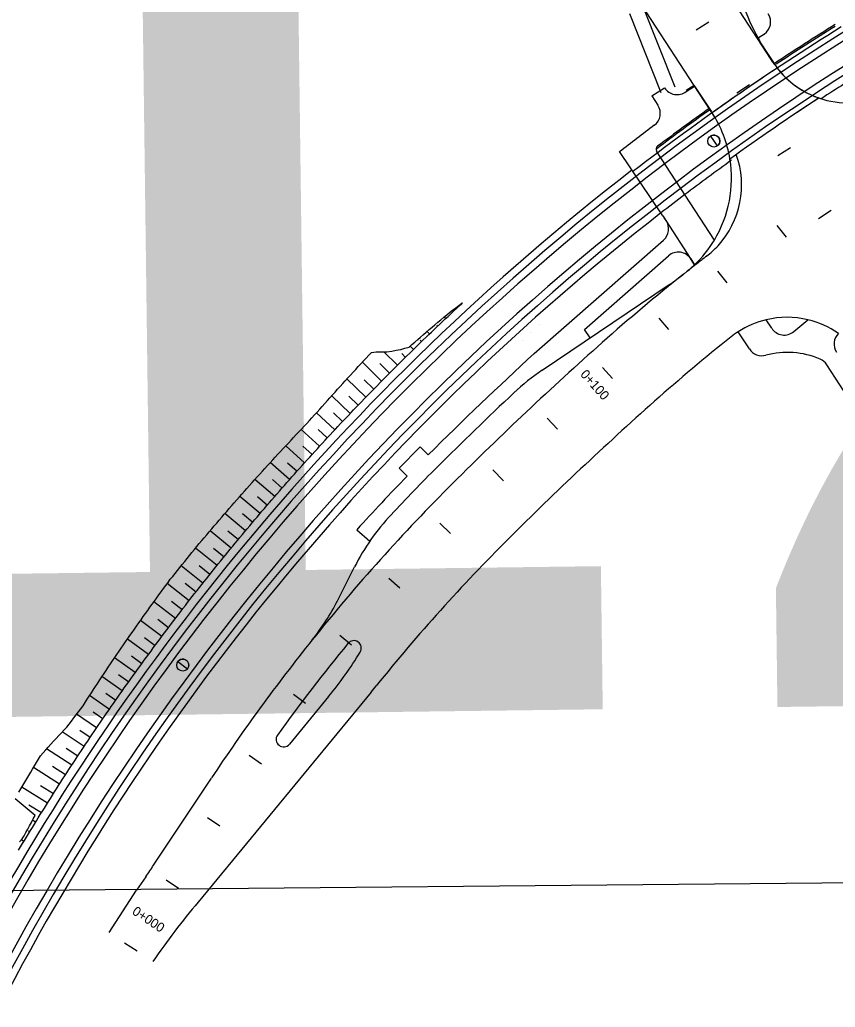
# Model space of a CAD drawing. Extents: x 6503541 to 6503743, y 5888004 to 5888145.
# Drawn here: x 6503659.417 to 6503662.029, y 5888075.351 to 5888078.516 of the extents above; entities that cross this region are included whole.
import ezdxf

# ---------------------------------------------------------------- set-up
doc = ezdxf.new("R2010")
doc.units = 0
doc.layers.add('12', color=7, linetype='Continuous')
doc.layers.add('tabela', color=7, linetype='Continuous')

msp = doc.modelspace()

# ---------------------------------------------------------------- linework, layer by layer
at = {"layer": '12'}
for p, q in [((6503661.7805, 5888078.4554), (6503661.1379, 5888079.444)), ((6503661.5776, 5888078.3052), (6503660.8946, 5888079.3559)), ((6503661.5165, 5888078.2997), (6503661.4141, 5888078.5568)), ((6503661.4719, 5888078.282), (6503661.3713, 5888078.5346)), ((6503661.8022, 5888078.4698), (6503661.7804, 5888078.4556)), ((6503661.7804, 5888078.4556), (6503661.8396, 5888078.3656)), ((6503661.81, 5888078.4101), (6503661.7805, 5888078.4554)), ((6503661.8299, 5888078.3797), (6503661.81, 5888078.4101)), ((6503661.5517, 5888078.2856), (6503661.5789, 5888078.3033)), ((6503661.5776, 5888078.3052), (6503661.5519, 5888078.2885)), ((6503661.6301, 5888078.2245), (6503661.5776, 5888078.3052)), ((6503661.5789, 5888078.3033), (6503661.6315, 5888078.2224)), ((6503661.4421, 5888078.2714), (6503661.4824, 5888078.2976)), ((6503661.4421, 5888078.2714), (6503661.4612, 5888078.2422)), ((6503661.6348, 5888078.2173), (6503661.6301, 5888078.2245)), ((6503661.644, 5888078.2032), (6503661.6301, 5888078.2245)), ((6503661.6348, 5888078.2173), (6503661.6349, 5888078.2171)), ((6503661.477, 5888077.8876), (6503661.3381, 5888078.093)), ((6503661.642, 5888077.8099), (6503661.4572, 5888078.0942)), ((6503661.477, 5888077.8876), (6503661.5768, 5888077.734)), ((6503661.4872, 5888077.8723), (6503661.481, 5888077.8814)), ((6503661.0651, 5888077.4464), (6503661.4791, 5888077.8093)), ((6503661.5789, 5888077.7308), (6503661.5568, 5888077.7649)), ((6503661.2256, 5888077.5233), (6503661.495, 5888077.7593)), ((6503661.5668, 5888077.7494), (6503661.5789, 5888077.7308)), ((6503661.0905, 5888077.3927), (6503661.4977, 5888077.667)), ((6503660.8346, 5888077.6079), (6503660.8339, 5888077.6087)), ((6503660.8068, 5888077.5849), (6503660.8082, 5888077.5834)), ((6503660.7819, 5888077.5588), (6503660.7769, 5888077.5641)), ((6503661.8257, 5888077.5273), (6503661.8082, 5888077.5543)), ((6503661.8968, 5888077.5166), (6503661.9419, 5888077.5543)), ((6503660.7297, 5888077.5092), (6503660.7221, 5888077.5172)), ((6503660.7526, 5888077.5374), (6503660.7558, 5888077.5341)), ((6503661.0537, 5888077.5136), (6503661.054, 5888077.5132)), ((6503661.0805, 5888077.5376), (6503661.0805, 5888077.5376)), ((6503661.2441, 5888077.4961), (6503661.2256, 5888077.5233)), ((6503661.7543, 5888077.461), (6503661.7186, 5888077.516)), ((6503660.6993, 5888077.4889), (6503660.7038, 5888077.4842)), ((6503661.0273, 5888077.4891), (6503661.027, 5888077.4894)), ((6503660.6267, 5888077.4086), (6503660.5835, 5888077.452)), ((6503660.678, 5888077.4591), (6503660.6675, 5888077.4698)), ((6503660.5759, 5888077.3576), (6503660.5142, 5888077.4185)), ((6503660.6406, 5888077.4458), (6503660.6523, 5888077.4339)), ((6503660.5702, 5888077.4141), (6503660.6012, 5888077.3831)), ((6503662.0996, 5888077.2602), (6503662.002, 5888077.4103)), ((6503660.5255, 5888077.3061), (6503660.4649, 5888077.3649)), ((6503660.5201, 5888077.3618), (6503660.5507, 5888077.3319)), ((6503660.4757, 5888077.2542), (6503660.4162, 5888077.3108)), ((6503660.4705, 5888077.3091), (6503660.5005, 5888077.2802)), ((6503660.4263, 5888077.2018), (6503660.3678, 5888077.2564)), ((6503660.4215, 5888077.2558), (6503660.4509, 5888077.2281)), ((6503660.3773, 5888077.149), (6503660.3185, 5888077.203)), ((6503660.3725, 5888077.2026), (6503660.4017, 5888077.1755)), ((6503660.3289, 5888077.0957), (6503660.2686, 5888077.1501)), ((6503660.3233, 5888077.1495), (6503660.3531, 5888077.1224)), ((6503660.6323, 5888077.0786), (6503660.6997, 5888077.147)), ((6503660.7253, 5888077.1217), (6503660.6997, 5888077.147)), ((6503660.2809, 5888077.042), (6503660.2192, 5888077.0967)), ((6503660.2743, 5888077.0962), (6503660.3049, 5888077.0689)), ((6503660.6323, 5888077.0786), (6503660.6579, 5888077.0534)), ((6503660.2335, 5888076.9879), (6503660.1703, 5888077.0428)), ((6503660.2259, 5888077.0424), (6503660.2571, 5888077.015)), ((6503660.1865, 5888076.9333), (6503660.1219, 5888076.9884)), ((6503660.178, 5888076.9882), (6503660.2099, 5888076.9607)), ((6503660.14, 5888076.8783), (6503660.074, 5888076.9336)), ((6503660.1305, 5888076.9335), (6503660.1632, 5888076.9059)), ((6503660.094, 5888076.8229), (6503660.0266, 5888076.8783)), ((6503660.0836, 5888076.8784), (6503660.117, 5888076.8507)), ((6503660.4968, 5888076.8816), (6503660.5378, 5888076.8446)), ((6503660.0486, 5888076.7671), (6503659.9798, 5888076.8226)), ((6503660.0372, 5888076.8228), (6503660.0713, 5888076.7951)), ((6503660.0036, 5888076.7108), (6503659.9337, 5888076.7662)), ((6503659.9913, 5888076.7668), (6503660.026, 5888076.739)), ((6503660.4345, 5888076.654), (6503660.4892, 5888076.7624)), ((6503659.9592, 5888076.6542), (6503659.8889, 5888076.7088)), ((6503659.9462, 5888076.7102), (6503659.9813, 5888076.6826)), ((6503659.9153, 5888076.5971), (6503659.8459, 5888076.65)), ((6503659.9023, 5888076.6526), (6503659.9372, 5888076.6257)), ((6503659.8591, 5888076.5945), (6503659.8935, 5888076.5685)), ((6503659.8719, 5888076.5397), (6503659.8036, 5888076.5908)), ((6503659.829, 5888076.4819), (6503659.7618, 5888076.5312)), ((6503659.8165, 5888076.5359), (6503659.8504, 5888076.5108)), ((6503659.7866, 5888076.4236), (6503659.7206, 5888076.4712)), ((6503659.7744, 5888076.477), (6503659.8077, 5888076.4528)), ((6503659.7448, 5888076.365), (6503659.6801, 5888076.4108)), ((6503659.733, 5888076.4177), (6503659.7657, 5888076.3944)), ((6503659.7036, 5888076.306), (6503659.6402, 5888076.3499)), ((6503659.6921, 5888076.358), (6503659.7241, 5888076.3356)), ((6503660.5423, 5888076.3612), (6503659.9879, 5888075.6883)), ((6503660.4063, 5888076.347), (6503660.2806, 5888076.1945)), ((6503659.6628, 5888076.2467), (6503659.5989, 5888076.2901)), ((6503659.6518, 5888076.2979), (6503659.6831, 5888076.2764)), ((6503659.6226, 5888076.1869), (6503659.5524, 5888076.2337)), ((6503659.6096, 5888076.239), (6503659.6426, 5888076.2168)), ((6503659.5651, 5888076.1817), (6503659.6027, 5888076.1569)), ((6503659.583, 5888076.1268), (6503659.5027, 5888076.1792)), ((6503659.5438, 5888076.0664), (6503659.4608, 5888076.1196)), ((6503659.5215, 5888076.1237), (6503659.5633, 5888076.0967)), ((6503659.5053, 5888076.0056), (6503659.4235, 5888076.0569)), ((6503659.4833, 5888076.0621), (6503659.5245, 5888076.036)), ((6503659.8456, 5888075.807), (6503660.0306, 5888076.086)), ((6503659.4457, 5888076.0002), (6503659.4862, 5888075.975)), ((6503659.4673, 5888075.9444), (6503659.4574, 5888075.9505)), ((6503659.4444, 5888075.9162), (6503659.4485, 5888075.9137)), ((6503659.4299, 5888075.8829), (6503659.4218, 5888075.8878)), ((6503659.8201, 5888075.7694), (6503659.7908, 5888075.727)), ((6503659.7034, 5888075.5913), (6503659.7908, 5888075.727))]:
    msp.add_line(p, q, dxfattribs=at)
for points in [[(6503661.5838, 5888078.4829), (6503661.624, 5888078.5091)], [(6503661.7146, 5888078.2817), (6503661.7548, 5888078.3079)], [(6503661.6292, 5888078.1425), (6503661.6516, 5888078.1113)], [(6503661.8454, 5888078.0805), (6503661.8856, 5888078.1066)], [(6503661.9762, 5888077.8793), (6503662.0164, 5888077.9054)], [(6503661.8729, 5888077.8186), (6503661.8436, 5888077.8567)], [(6503661.6827, 5888077.6723), (6503661.6534, 5888077.7103)], [(6503659.413, 5888075.8548), (6503659.4192, 5888075.8652), (6503659.4255, 5888075.8757), (6503659.4318, 5888075.8861), (6503659.438, 5888075.8965), (6503659.4444, 5888075.9069), (6503659.4507, 5888075.9173), (6503659.457, 5888075.9277), (6503659.4634, 5888075.9381), (6503659.4698, 5888075.9484), (6503659.4761, 5888075.9588), (6503659.4825, 5888075.9691), (6503659.489, 5888075.9795), (6503659.4954, 5888075.9898), (6503659.5019, 5888076.0001), (6503659.5083, 5888076.0104), (6503659.5148, 5888076.0207), (6503659.5213, 5888076.031), (6503659.5278, 5888076.0413), (6503659.5344, 5888076.0515), (6503659.5409, 5888076.0618), (6503659.5475, 5888076.072), (6503659.554, 5888076.0823), (6503659.5606, 5888076.0925), (6503659.5672, 5888076.1027), (6503659.5739, 5888076.1129), (6503659.5805, 5888076.1231), (6503659.5872, 5888076.1333), (6503659.5938, 5888076.1435), (6503659.6005, 5888076.1536), (6503659.6072, 5888076.1638), (6503659.614, 5888076.1739), (6503659.6207, 5888076.1841), (6503659.6274, 5888076.1942), (6503659.6342, 5888076.2043), (6503659.641, 5888076.2144), (6503659.6478, 5888076.2245), (6503659.6546, 5888076.2346), (6503659.6614, 5888076.2446), (6503659.6683, 5888076.2547), (6503659.6751, 5888076.2647), (6503659.682, 5888076.2748), (6503659.6889, 5888076.2848), (6503659.6958, 5888076.2948), (6503659.7027, 5888076.3048), (6503659.7097, 5888076.3148), (6503659.7166, 5888076.3248), (6503659.7236, 5888076.3348), (6503659.7306, 5888076.3448), (6503659.7376, 5888076.3547), (6503659.7446, 5888076.3647), (6503659.7516, 5888076.3746), (6503659.7586, 5888076.3845), (6503659.7657, 5888076.3944), (6503659.7728, 5888076.4043), (6503659.7799, 5888076.4142), (6503659.787, 5888076.4241), (6503659.7941, 5888076.434), (6503659.8012, 5888076.4438), (6503659.8084, 5888076.4537), (6503659.8155, 5888076.4635), (6503659.8227, 5888076.4733), (6503659.8299, 5888076.4831), (6503659.8371, 5888076.4929), (6503659.8444, 5888076.5027), (6503659.8516, 5888076.5125), (6503659.8588, 5888076.5223), (6503659.8661, 5888076.532), (6503659.8734, 5888076.5418), (6503659.8807, 5888076.5515), (6503659.888, 5888076.5612), (6503659.8954, 5888076.5709), (6503659.9027, 5888076.5806), (6503659.9101, 5888076.5903), (6503659.9174, 5888076.6), (6503659.9248, 5888076.6097), (6503659.9322, 5888076.6193), (6503659.9396, 5888076.629), (6503659.9471, 5888076.6386), (6503659.9545, 5888076.6482), (6503659.962, 5888076.6578), (6503659.9695, 5888076.6674), (6503659.977, 5888076.677), (6503659.9845, 5888076.6866), (6503659.992, 5888076.6961), (6503659.9995, 5888076.7057), (6503660.0071, 5888076.7152), (6503660.0147, 5888076.7247), (6503660.0222, 5888076.7343), (6503660.0298, 5888076.7438), (6503660.0375, 5888076.7533), (6503660.0451, 5888076.7627), (6503660.0527, 5888076.7722), (6503660.0604, 5888076.7817), (6503660.068, 5888076.7911), (6503660.0757, 5888076.8005), (6503660.0834, 5888076.81), (6503660.0911, 5888076.8194), (6503660.0989, 5888076.8288), (6503660.1066, 5888076.8382), (6503660.1144, 5888076.8475), (6503660.1221, 5888076.8569), (6503660.1299, 5888076.8663), (6503660.1377, 5888076.8756), (6503660.1455, 5888076.8849), (6503660.1534, 5888076.8942), (6503660.1612, 5888076.9035), (6503660.1691, 5888076.9128), (6503660.1769, 5888076.9221), (6503660.1848, 5888076.9314), (6503660.1927, 5888076.9406), (6503660.2006, 5888076.9499), (6503660.2086, 5888076.9591), (6503660.2165, 5888076.9683), (6503660.2245, 5888076.9775), (6503660.2324, 5888076.9867), (6503660.2404, 5888076.9959), (6503660.2484, 5888077.0051), (6503660.2564, 5888077.0142), (6503660.2645, 5888077.0234), (6503660.2725, 5888077.0325), (6503660.2806, 5888077.0416), (6503660.2886, 5888077.0507), (6503660.2967, 5888077.0598), (6503660.3048, 5888077.0689), (6503660.3129, 5888077.078), (6503660.321, 5888077.087), (6503660.3292, 5888077.0961), (6503660.3373, 5888077.1051), (6503660.3455, 5888077.1141), (6503660.3537, 5888077.1231), (6503660.3619, 5888077.1321), (6503660.3701, 5888077.1411), (6503660.3783, 5888077.1501), (6503660.3865, 5888077.159), (6503660.3948, 5888077.168), (6503660.4031, 5888077.1769), (6503660.4113, 5888077.1858), (6503660.4196, 5888077.1947), (6503660.4279, 5888077.2036), (6503660.4362, 5888077.2125), (6503660.4446, 5888077.2214), (6503660.4529, 5888077.2302), (6503660.4613, 5888077.239), (6503660.4697, 5888077.2479), (6503660.478, 5888077.2567), (6503660.4864, 5888077.2655), (6503660.4949, 5888077.2743), (6503660.5033, 5888077.2831), (6503660.5117, 5888077.2918), (6503660.5202, 5888077.3006), (6503660.5286, 5888077.3093), (6503660.5371, 5888077.318), (6503660.5456, 5888077.3267), (6503660.5541, 5888077.3354), (6503660.5626, 5888077.3441), (6503660.5712, 5888077.3528), (6503660.5797, 5888077.3615), (6503660.5883, 5888077.3701), (6503660.5969, 5888077.3787), (6503660.6054, 5888077.3874), (6503660.614, 5888077.396), (6503660.6227, 5888077.4046), (6503660.6313, 5888077.4131), (6503660.6399, 5888077.4217), (6503660.6486, 5888077.4303), (6503660.6573, 5888077.4388), (6503660.6659, 5888077.4473), (6503660.6746, 5888077.4558), (6503660.6833, 5888077.4643), (6503660.6921, 5888077.4728), (6503660.7008, 5888077.4813), (6503660.7095, 5888077.4898), (6503660.7183, 5888077.4982), (6503660.7271, 5888077.5066), (6503660.7358, 5888077.5151), (6503660.7446, 5888077.5235), (6503660.7534, 5888077.5319), (6503660.7623, 5888077.5402), (6503660.7711, 5888077.5486), (6503660.78, 5888077.5569), (6503660.7888, 5888077.5653), (6503660.7977, 5888077.5736), (6503660.8066, 5888077.5819), (6503660.8155, 5888077.5902), (6503660.8244, 5888077.5985), (6503660.8333, 5888077.6068), (6503660.8346, 5888077.6079)], [(6503659.414, 5888076.0406), (6503659.4202, 5888076.0512), (6503659.4265, 5888076.0619), (6503659.4327, 5888076.0725), (6503659.439, 5888076.0831), (6503659.4453, 5888076.0937), (6503659.4516, 5888076.1043), (6503659.4579, 5888076.1148), (6503659.4643, 5888076.1254), (6503659.4706, 5888076.136), (6503659.477, 5888076.1465), (6503659.4834, 5888076.1571), (6503659.4913, 5888076.1666), (6503659.4997, 5888076.1759), (6503659.508, 5888076.1851), (6503659.5164, 5888076.1943), (6503659.5248, 5888076.2035), (6503659.5332, 5888076.2127), (6503659.5416, 5888076.2219), (6503659.55, 5888076.2311), (6503659.5585, 5888076.2403), (6503659.5669, 5888076.2494), (6503659.5748, 5888076.2589), (6503659.5823, 5888076.2686), (6503659.5898, 5888076.2784), (6503659.5974, 5888076.2882), (6503659.6049, 5888076.2979), (6503659.6124, 5888076.3076), (6503659.6194, 5888076.3177), (6503659.626, 5888076.3281), (6503659.6327, 5888076.3384), (6503659.6394, 5888076.3487), (6503659.6461, 5888076.359), (6503659.6528, 5888076.3693), (6503659.6595, 5888076.3796), (6503659.6663, 5888076.3899), (6503659.6731, 5888076.4001), (6503659.6798, 5888076.4104), (6503659.6867, 5888076.4206), (6503659.6935, 5888076.4309), (6503659.7003, 5888076.4411), (6503659.7072, 5888076.4513), (6503659.7141, 5888076.4615), (6503659.7209, 5888076.4717), (6503659.7279, 5888076.4818), (6503659.7348, 5888076.492), (6503659.7417, 5888076.5021), (6503659.7487, 5888076.5123), (6503659.7557, 5888076.5224), (6503659.7627, 5888076.5325), (6503659.7697, 5888076.5426), (6503659.7767, 5888076.5527), (6503659.7838, 5888076.5628), (6503659.7909, 5888076.5728), (6503659.7979, 5888076.5829), (6503659.8051, 5888076.5929), (6503659.8122, 5888076.603), (6503659.8193, 5888076.613), (6503659.8265, 5888076.623), (6503659.8336, 5888076.633), (6503659.8408, 5888076.643), (6503659.848, 5888076.653), (6503659.8553, 5888076.6629), (6503659.8625, 5888076.6729), (6503659.8698, 5888076.6828), (6503659.8771, 5888076.6927), (6503659.8843, 5888076.7026), (6503659.8917, 5888076.7125), (6503659.8986, 5888076.7227), (6503659.9066, 5888076.7321), (6503659.9141, 5888076.7418), (6503659.9218, 5888076.7514), (6503659.9295, 5888076.761), (6503659.9372, 5888076.7706), (6503659.945, 5888076.7802), (6503659.9527, 5888076.7897), (6503659.9605, 5888076.7993), (6503659.9683, 5888076.8088), (6503659.9762, 5888076.8182), (6503659.984, 5888076.8277), (6503659.9919, 5888076.8372), (6503659.9998, 5888076.8466), (6503660.0078, 5888076.856), (6503660.0157, 5888076.8654), (6503660.0236, 5888076.8748), (6503660.0316, 5888076.8842), (6503660.0396, 5888076.8935), (6503660.0476, 5888076.9029), (6503660.0556, 5888076.9122), (6503660.0636, 5888076.9216), (6503660.0716, 5888076.9309), (6503660.0797, 5888076.9402), (6503660.0877, 5888076.9495), (6503660.0958, 5888076.9587), (6503660.1039, 5888076.968), (6503660.112, 5888076.9773), (6503660.1202, 5888076.9865), (6503660.1283, 5888076.9957), (6503660.1364, 5888077.0049), (6503660.1446, 5888077.0141), (6503660.1528, 5888077.0233), (6503660.161, 5888077.0325), (6503660.1692, 5888077.0416), (6503660.1774, 5888077.0508), (6503660.1857, 5888077.0599), (6503660.1939, 5888077.069), (6503660.2022, 5888077.0781), (6503660.2105, 5888077.0872), (6503660.2188, 5888077.0963), (6503660.2271, 5888077.1053), (6503660.2354, 5888077.1144), (6503660.2438, 5888077.1234), (6503660.2521, 5888077.1324), (6503660.2605, 5888077.1414), (6503660.2689, 5888077.1504), (6503660.2773, 5888077.1594), (6503660.2857, 5888077.1684), (6503660.2941, 5888077.1773), (6503660.3025, 5888077.1862), (6503660.311, 5888077.1952), (6503660.3195, 5888077.2041), (6503660.328, 5888077.213), (6503660.3362, 5888077.222), (6503660.3445, 5888077.2311), (6503660.3528, 5888077.2402), (6503660.3612, 5888077.2492), (6503660.3695, 5888077.2583), (6503660.3777, 5888077.2674), (6503660.3858, 5888077.2766), (6503660.394, 5888077.2859), (6503660.4021, 5888077.2951), (6503660.4103, 5888077.3042), (6503660.4185, 5888077.3134), (6503660.4267, 5888077.3226), (6503660.4349, 5888077.3317), (6503660.4432, 5888077.3409), (6503660.4514, 5888077.35), (6503660.4597, 5888077.3591), (6503660.468, 5888077.3682), (6503660.4763, 5888077.3773), (6503660.4846, 5888077.3864), (6503660.4929, 5888077.3954), (6503660.5013, 5888077.4045), (6503660.5096, 5888077.4135), (6503660.518, 5888077.4225), (6503660.5264, 5888077.4315), (6503660.5348, 5888077.4404), (6503660.5433, 5888077.4493), (6503660.5588, 5888077.4512), (6503660.5754, 5888077.452), (6503660.5927, 5888077.452), (6503660.6082, 5888077.4538), (6503660.6227, 5888077.4565), (6503660.6371, 5888077.4593), (6503660.6507, 5888077.4629), (6503660.664, 5888077.4667), (6503660.6732, 5888077.4748), (6503660.6824, 5888077.4828), (6503660.6916, 5888077.4908), (6503660.7008, 5888077.4988), (6503660.71, 5888077.5068), (6503660.7192, 5888077.5148), (6503660.7285, 5888077.5227), (6503660.7377, 5888077.5307), (6503660.747, 5888077.5386), (6503660.7563, 5888077.5466), (6503660.7655, 5888077.5545), (6503660.7748, 5888077.5624), (6503660.7844, 5888077.57), (6503660.794, 5888077.5775), (6503660.8036, 5888077.5851), (6503660.8133, 5888077.5926), (6503660.8229, 5888077.6001), (6503660.8339, 5888077.6087)], [(6503661.4962, 5888077.5227), (6503661.4654, 5888077.5595)], [(6503661.2836, 5888077.4016), (6503661.3157, 5888077.3659)], [(6503661.1391, 5888077.2041), (6503661.1063, 5888077.2392)], [(6503660.966, 5888077.0386), (6503660.9324, 5888077.073)], [(6503660.797, 5888076.8693), (6503660.7624, 5888076.9026)], [(6503660.6346, 5888076.6938), (6503660.5987, 5888076.7257)], [(6503660.4794, 5888076.5121), (6503660.4423, 5888076.5425)], [(6503659.9235, 5888076.4592), (6503659.9543, 5888076.4363)], [(6503660.3316, 5888076.3242), (6503660.2933, 5888076.3531)], [(6503660.1914, 5888076.1306), (6503660.152, 5888076.158)], [(6503659.4161, 5888075.8813), (6503659.4243, 5888075.8906), (6503659.4307, 5888075.9009), (6503659.4365, 5888075.9117), (6503659.4422, 5888075.9225), (6503659.448, 5888075.9332), (6503659.4538, 5888075.9439), (6503659.4596, 5888075.9547), (6503659.4655, 5888075.9654), (6503659.4016, 5888076.0193)], [(6503660.0579, 5888075.9318), (6503660.0179, 5888075.9583)], [(6503659.9253, 5888075.7318), (6503659.8853, 5888075.7583)], [(6503659.7526, 5888075.5583), (6503659.7926, 5888075.5318)]]:
    msp.add_lwpolyline(points, dxfattribs=at)
for centre in [(6503661.6404, 5888078.1269), (6503659.9389, 5888076.4477)]:
    msp.add_circle(centre, 0.0192, dxfattribs=at)
for centre, radius, start, end in [((6503662.4137, 5888078.8025), 0.72, 198.9918, 208.6999), ((6503666.2038, 5888071.8011), 7.8588, 121.15983, 152.60981), ((6503661.7744, 5888078.5089), 0.048, 305.3594, 33.0281), ((6503666.2038, 5888071.8011), 7.8348, 121.15983, 152.60981), ((6503666.2038, 5888071.8011), 7.8768, 121.83974, 127.75161), ((6503666.2038, 5888071.8011), 7.8936, 121.92697, 123.61654), ((6503666.2038, 5888071.8011), 7.8888, 121.95498, 123.5863), ((6503666.2038, 5888071.8011), 7.7652, 121.15983, 152.60981), ((6503662.4137, 5888078.8025), 0.72, 208.6999, 213.0274), ((6503666.2038, 5888071.8011), 7.7412, 121.15983, 152.60981), ((6503662.071, 5888078.5372), 0.288, 213.156, 217.7519), ((6503662.0708, 5888078.5373), 0.288, 216.6058, 252.5232), ((6503666.2038, 5888071.8011), 7.8768, 123.61377, 125.45523), ((6503662.071, 5888078.5372), 0.288, 217.7519, 250.9331), ((6503666.2038, 5888071.8011), 7.7172, 121.83974, 123.14553), ((6503661.5226, 5888078.3238), 0.048, 213.0281, 307.2991), ((6503662.071, 5888078.5372), 0.288, 250.9331, 293.3313), ((6503661.4209, 5888078.216), 0.048, 306.6818, 33.0281), ((6503666.2038, 5888071.8011), 7.7232, 123.18191, 125.74594), ((6503666.2038, 5888071.8011), 7.7232, 123.18107, 125.74594), ((6503666.2038, 5888071.8011), 7.8888, 125.45154, 126.9871), ((6503666.2038, 5888071.8011), 7.8936, 125.45006, 126.93905), ((6503661.313, 5888078.0078), 0.384, 9.2332, 33.0281), ((6503661.313, 5888078.0078), 0.384, 9.2332, 33.0281), ((6503666.2332, 5888071.7556), 8.0077, 126.68184, 127.68264), ((6503661.6404, 5888078.1269), 0.0192, 1.3596, 125.8068), ((6503661.6404, 5888078.1269), 0.0192, 305.8068, 1.3596), ((6503661.4673, 5888078.1007), 0.012, 126.9391, 213.0281), ((6503661.4414, 5888077.9863), 0.288, 317.5056, 19.8301), ((6503666.2038, 5888071.8011), 7.7172, 125.72958, 127.11182), ((6503661.313, 5888078.0078), 0.384, 328.9725, 9.2332), ((6503661.313, 5888078.0078), 0.384, 8.2282, 9.2332), ((6503666.2038, 5888071.8011), 7.8828, 127.74879, 152.60981), ((6503666.2038, 5888071.8011), 7.7172, 127.11182, 127.82816), ((6503666.2038, 5888071.8011), 7.7172, 127.82816, 152.60981), ((6503661.4475, 5888077.8454), 0.048, 311.2313, 34.1817), ((6503661.313, 5888078.0078), 0.384, 313.835, 328.9725), ((6503661.313, 5888078.0078), 0.384, 313.835, 328.9725), ((6503661.5266, 5888077.7232), 0.048, 33.0281, 131.2313), ((6503661.4414, 5888077.9863), 0.288, 307.6003, 317.5056), ((6503665.3806, 5888072.8713), 6.168, 127.57945, 128.03818), ((6503665.3806, 5888072.8713), 6.168, 128.37582, 128.47072), ((6503661.313, 5888078.0078), 0.384, 308.3758, 313.835), ((6503665.3806, 5888072.8713), 6.168, 128.03818, 128.37582), ((6503665.3806, 5888072.8713), 6.168, 128.47072, 131.63003), ((6503661.0954, 5888078.2641), 0.72, 303.9671, 308.4707), ((6503661.875, 5888077.2742), 0.288, 103.418, 122.8972), ((6503661.875, 5888077.2742), 0.288, 76.5702, 103.418), ((6503661.875, 5888077.2742), 0.288, 55.1612, 76.5702), ((6503661.875, 5888077.2742), 0.288, 122.8972, 128.5269), ((6503661.866, 5888077.5534), 0.048, 213.0281, 309.894), ((6503668.8802, 5888068.9337), 11.436, 131.63003, 134.92387), ((6503665.3806, 5888072.8713), 5.916, 128.52692, 131.63003), ((6503662.0734, 5888077.4766), 0.048, 134.9067, 213.0281), ((6503661.7946, 5888077.4872), 0.048, 213.0281, 285.1078), ((6503661.8759, 5888077.1859), 0.264, 66.5854, 105.1078), ((6503668.8802, 5888068.9337), 11.556, 132.55346, 134.88414), ((6503661.9617, 5888077.3842), 0.048, 33.0281, 66.5854), ((6503661.4928, 5888076.7955), 0.72, 123.9671, 133.2181), ((6503668.8802, 5888068.9337), 11.508, 133.21808, 134.92387), ((6503668.8802, 5888068.9337), 11.184, 131.62998, 134.92387), ((6503665.1008, 5888072.7232), 6.156, 134.92387, 136.89657), ((6503665.1008, 5888072.7232), 6.204, 135.73646, 137.91106), ((6503665.1008, 5888072.7232), 6.084, 134.92387, 141.28541), ((6503661.1319, 5888076.4377), 0.72, 136.8966, 153.196), ((6503665.1008, 5888072.7232), 5.832, 134.92387, 141.14755), ((6503659.7918, 5888076.9787), 0.72, 321.2855, 333.196), ((6503665.1008, 5888072.7232), 6.084, 141.28546, 146.44549), ((6503665.1008, 5888072.7232), 5.988, 140.68266, 144.22577), ((6503660.4868, 5888076.5021), 0.024, 328.8685, 140.6842), ((6503659.9389, 5888076.4477), 0.0192, 18.989, 143.4363), ((6503659.4801, 5888077.1101), 1.2, 320.5154, 328.8685), ((6503659.9389, 5888076.4477), 0.0192, 323.4363, 18.989), ((6503658.69, 5888077.8873), 2.4, 320.5154, 321.1476), ((6503660.262, 5888076.2097), 0.024, 144.2258, 320.5154), ((6503657.8455, 5888077.1336), 2.4, 325.3623, 326.4455), ((6503661.8263, 5888074.1455), 2.4, 139.9957, 145.7103)]:
    msp.add_arc(centre, radius, start, end, dxfattribs=at)
at = {"layer": 'tabela'}
msp.add_line((6503665.9808, 5888075.7866), (6503658.7454, 5888075.7191), dxfattribs=at)
msp.add_line((6503665.9808, 5888075.7866), (6503658.7454, 5888075.7191), dxfattribs=at)

# ---------------------------------------------------------------- texts
at = {"layer": '12'}
for s, height, rotation, p in [('12', 4.22297, 0.7393, (6503658.4198, 5888076.2693)), ('0+100', 0.03, 311.8955, (6503661.2106, 5888077.3781)), ('0+000', 0.03, 326.4455, (6503659.7741, 5888075.6519)), ('0+000', 0.03, 326.4455, (6503659.7741, 5888075.6519))]:
    msp.add_text(s, height=height, rotation=rotation, dxfattribs=at).set_placement(p)

doc.saveas('drawing.dxf')
